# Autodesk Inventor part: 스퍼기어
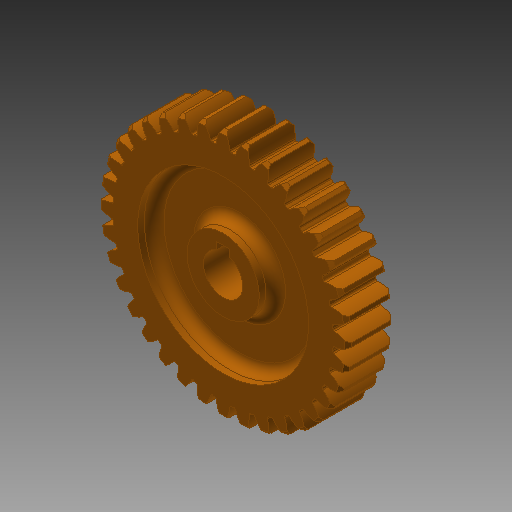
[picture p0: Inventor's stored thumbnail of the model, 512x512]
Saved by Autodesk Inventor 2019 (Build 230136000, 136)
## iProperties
Created: 2019-01
Part Number: 스퍼기어
Material: 강철, 주조
Document SubType Name: Modeling
Designer: mduedu
Density: 7.85 g/cm^3
Mass: 107.477 g
Surface Area: 168.408 cm^2
Volume: 39.6595 cm^3
Appearance: 주황색
Author: mduedu
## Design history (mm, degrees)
sketch "스케치1"
  geometry: C1 r 33.5 at (0, 0); C2 r 36 at (0, 0); C3 r 38 at (0, 0); 1 further point
  constraints: 3 centre point, 3 coincident
  dimensions: "d0" = 67 diameter of C1; "d2" = 72 diameter of C2; "d3" = 76 diameter of C3
extrude "돌출1" new body sketch "스케치1" distance "d4" = 14; taper "d5" = 0 deg
sketch "스케치2"
  geometry: L1 (0, 0)-(-38, 0); L2 (0, 0)-(0, 38); L3 (-0.57, 0)-(-0.57, 37.996); L4 (-1.57, 0)-(-1.57, 35.966); L5 (-2.07, 0)-(-2.07, 33.436); A1 r 38 centre (0, 0) between (-38, 0) and (0, 38) reference; A2 r 9.246 centre (7.162, 32.926) between (-0.57, 37.996) and (-2.07, 33.436); A3 r 9.246 centre (-7.162, 32.926) between (2.07, 33.436) and (0.57, 37.996); A4 r 33.5 centre (0, 0) between (2.07, 33.436) and (-2.07, 33.436); A5 r 38 centre (0, 0) between (0.57, 37.996) and (-0.57, 37.996); 2 further points
  constraints: 12 point on circle, 10 end point, 4 centre point, 3 parallel, 3 symmetric about line, 2 coincident, 1 horizontal, 1 perpendicular, 5 other
  dimensions: "d6" = 0.5 distance between parallel lines of L4 L5; "d8" = 1 distance between parallel lines of L3 L4; "d9" = 1.57 distance between parallel lines of L2 L4
extrude "돌출2" join sketch "스케치2" stored distance "d10" = 14; taper "d11" = 0 deg
chamfer "모따기1" distance "d12" = 1; stored, may be unused: second distance "d13" = 2, angle "d14" = 45 deg
fillet "모깎기1" dims "d15" = 0.5
sketch "스케치3"
  geometry: C1 r 11 at (0, 0); 1 further point
  constraints: 1 centre point, 1 coincident
  dimensions: "d19" = 22 diameter of C1
extrude "돌출3" join sketch "스케치3" distance "d20" = 6; taper "d21" = 0 deg
sketch "스케치4"
  geometry: C1 r 11 at (0, 0); C2 r 26 at (0, 0); 1 further point
  constraints: 2 centre point, 2 coincident
  dimensions: "d23" = 22 diameter of C1; "d24" = 52 diameter of C2
extrude "돌출4" cut sketch "스케치4" distance "d25" = 5; taper "d26" = 0 deg
fillet "모깎기3" dims "d27" = 3
node "작업 평면1"
sketch "스케치5" dims "d28" = 60
  geometry: C1 r 1.5 at (0, 30); 2 further points
  constraints: 2 vertical alignment, 1 centre point, 1 coincident, 2 other
  dimensions: "d29" = 3 diameter of C1
extrude "돌출5" join sketch "스케치5" distance "d30" = 0.5; taper "d31" = 0 deg
sketch "스케치6"
  geometry: L1 (-2, 5.657)-(2, 5.657); L2 (2, 5.657)-(2, 7.8); L3 (2, 7.8)-(-2, 7.8); L4 (-2, 7.8)-(-2, 5.657); A1 r 6 centre (0, 0) between (-2, 5.657) and (2, 5.657); 1 further point
  constraints: 8 end point, 2 parallel, 2 point on circle, 1 centre point, 1 coincident, 1 horizontal, 1 perpendicular
  dimensions: "d32" = 13.8 dimension on A1 L3; "d34" = 4 distance of L2.end L3.end; "d35" = 12 diameter of A1
extrude "돌출6" cut sketch "스케치6" extent not by distance; stored distance "d36" = 0.5; taper "d37" = 0 deg
chamfer "모따기2" distance "d38" = 1; stored, may be unused: second distance "d39" = 2, angle "d40" = 45 deg
feature "면 이동1"
node "솔리드1"
pattern_circular "원형 패턴1" dims angle "d17" = 360 deg
mirror "대칭1"
